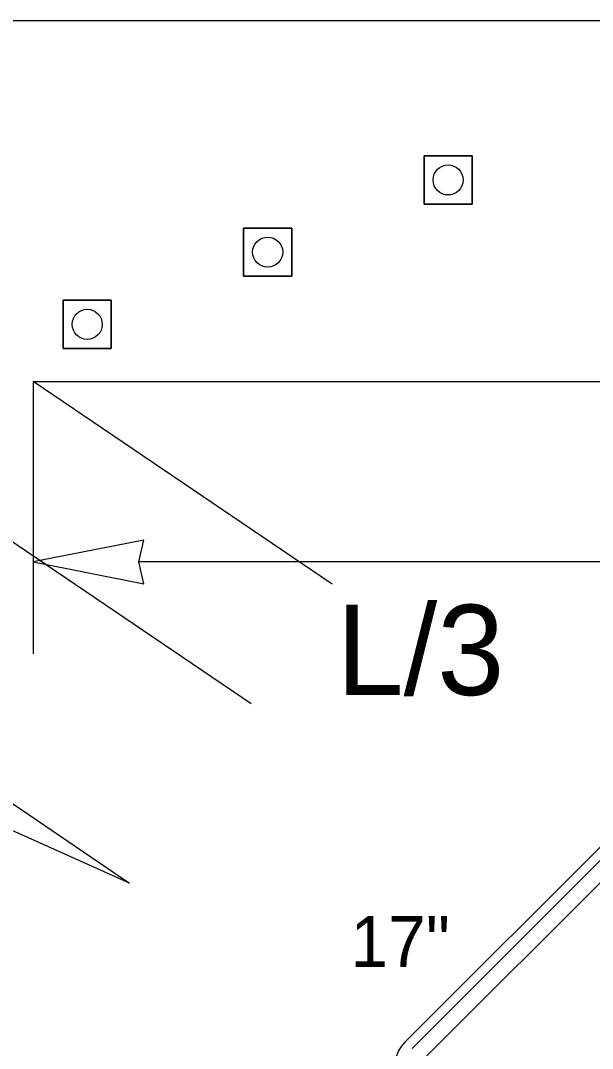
# Model space of a CAD drawing. Extents: x 99999.1 to 100055.7, y 99995 to 100013.2.
# Drawn here: x 100024.086 to 100024.593, y 100006.2 to 100007.111 of the extents above; entities that cross this region are included whole.
import ezdxf

# ---------------------------------------------------------------- set-up
doc = ezdxf.new("R2010")
doc.units = 0
for name, color, linetype in [('RD_MK_LineEdgeYellow', 7, 'Continuous'), ('TR_SN_ConstructionSigns', 7, 'Continuous'), ('TR_WZ_TrafficCone', 7, 'Continuous'), ('TR_WZ_WorkZoneDetails', 7, 'Continuous'), ('TR_WZ_WorkZoneTextCurrent', 7, 'Continuous')]:
    doc.layers.add(name, color=color, linetype=linetype)

msp = doc.modelspace()

# ---------------------------------------------------------------- linework, layer by layer
at = {"layer": 'RD_MK_LineEdgeYellow'}
for p, q in [((100024.09678, 100007.11091), (100027.555, 100007.11091)), ((100024.29003, 100006.50516), (100024.02488, 100006.68488))]:
    msp.add_line(p, q, dxfattribs=at)
at = {"layer": 'TR_SN_ConstructionSigns'}
for p, q in [((100024.76094, 100006.53962), (100024.42684, 100006.20551)), ((100024.76691, 100006.53365), (100024.4328, 100006.19955)), ((100024.44275, 100006.1896), (100024.77685, 100006.52371))]:
    msp.add_line(p, q, dxfattribs=at)
msp.add_arc((100024.4507, 100006.18165), 0.03375, 135, 225.00001, dxfattribs=at)
at = {"layer": 'TR_WZ_TrafficCone'}
for points in [[(100024.44348, 100006.99091), (100024.48614, 100006.99091), (100024.48614, 100006.94825), (100024.44348, 100006.94825), (100024.44348, 100006.99091)], [(100024.44348, 100006.94825), (100024.48614, 100006.94825), (100024.48614, 100006.99091), (100024.44348, 100006.99091), (100024.44348, 100006.94825)], [(100024.28348, 100006.92691), (100024.32614, 100006.92691), (100024.32614, 100006.88425), (100024.28348, 100006.88425), (100024.28348, 100006.92691)], [(100024.28348, 100006.88425), (100024.32614, 100006.88425), (100024.32614, 100006.92691), (100024.28348, 100006.92691), (100024.28348, 100006.88425)], [(100024.12344, 100006.8629), (100024.16611, 100006.8629), (100024.16611, 100006.82024), (100024.12344, 100006.82024), (100024.12344, 100006.8629)], [(100024.12344, 100006.82024), (100024.16611, 100006.82024), (100024.16611, 100006.8629), (100024.12344, 100006.8629), (100024.12344, 100006.82024)]]:
    msp.add_lwpolyline(points, dxfattribs=at)
for centre in [(100024.46481, 100006.96958), (100024.30481, 100006.90558), (100024.14478, 100006.84157)]:
    msp.add_circle(centre, 0.01333, dxfattribs=at)
at = {"layer": 'TR_WZ_WorkZoneDetails'}
for p, q in [((100023.39635, 100007.11091), (100024.09678, 100007.11091)), ((100024.36187, 100006.61114), (100024.09678, 100006.79091)), ((100024.09678, 100006.79091), (100027.555, 100006.79091)), ((100024.09678, 100006.79091), (100024.09678, 100006.5495)), ((100024.69108, 100006.63091), (100024.19051, 100006.63091))]:
    msp.add_line(p, q, dxfattribs=at)
for points in [[(100024.09678, 100006.63091), (100024.19506, 100006.61163), (100024.19051, 100006.63091), (100024.19506, 100006.65018)], [(100024.18231, 100006.34623), (100024.02009, 100006.41891), (100024.05216, 100006.43444)]]:
    msp.add_lwpolyline(points, close=True, dxfattribs=at)

# ---------------------------------------------------------------- texts
at = {"layer": 'TR_SN_ConstructionSigns'}
msp.add_text('17"', height=0.045, dxfattribs=at).set_placement((100024.37814, 100006.27189))
at = {"layer": 'TR_WZ_WorkZoneTextCurrent'}
msp.add_text('L/3', height=0.08, dxfattribs=at).set_placement((100024.36591, 100006.51291))

doc.saveas('drawing.dxf')
